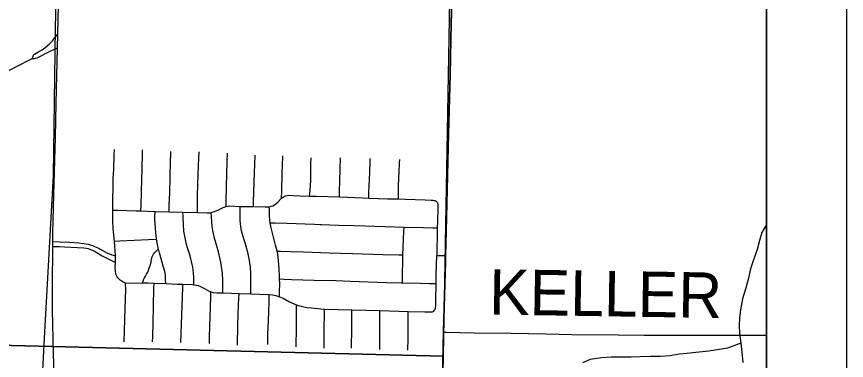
# Model space of a CAD drawing. Extents: x 0 to 34, y 0 to 22.
# Drawn here: x 7.962 to 9, y 16.878 to 17.308 of the extents above; entities that cross this region are included whole.
import ezdxf

# ---------------------------------------------------------------- set-up
doc = ezdxf.new("R2010")
doc.units = 0
for name, color, linetype in [('GM_X_Corporation', 7, 'Continuous'), ('GM_X_County_Road', 7, 'Continuous'), ('GM_X_Minor_River', 7, 'Continuous'), ('GM_X_Township_Road', 7, 'Continuous'), ('GM_X_Township_Road_Text', 7, 'Continuous'), ('SH_Data', 7, 'Continuous')]:
    doc.layers.add(name, color=color, linetype=linetype)

msp = doc.modelspace()

# ---------------------------------------------------------------- linework, layer by layer
at = {"layer": 'GM_X_Corporation'}
for points in [[(2.1, 14.1), (8.9, 14.1), (8.9, 20.9), (5.8906, 20.9)], [(8.9, 14.3789), (8.9, 20.9)], [(8.5071, 17.3567), (8.5056, 17.3001), (8.5042, 17.2361), (8.5017, 17.1453), (8.5005, 17.0919), (8.4991, 17.039), (8.4984, 17.0094), (8.4982, 17.0005), (8.4971, 16.9595), (8.496, 16.9136), (8.4946, 16.8569)], [(8.4946, 16.8569), (8.496, 16.9136), (8.4971, 16.9595), (8.4982, 17.0005), (8.4984, 17.0094), (8.4991, 17.039), (8.5005, 17.0919), (8.5017, 17.1453), (8.5042, 17.2361), (8.5056, 17.3001), (8.5071, 17.3567)]]:
    msp.add_lwpolyline(points, dxfattribs=at)
for points in [[(7.515, 17.8763), (8.5579, 17.8652), (8.5553, 17.7758), (8.5049, 17.4227), (8.4956, 16.8828), (7.4991, 16.9078)], [(8.9, 16.4075), (8.9, 17.4164), (8.5049, 17.4227), (8.4956, 16.8828), (8.4859, 16.4125)], [(7.4991, 16.9078), (8.4956, 16.8828), (8.4859, 16.4125), (8.4788, 15.8782), (7.4758, 15.8976)]]:
    msp.add_lwpolyline(points, close=True, dxfattribs=at)
at = {"layer": 'GM_X_County_Road'}
for points in [[(8.4986, 17.0089), (8.4994, 17.0385), (8.5008, 17.0913), (8.502, 17.1448), (8.5044, 17.2355), (8.5058, 17.2995), (8.5074, 17.3561), (8.5081, 17.3847), (8.5084, 17.3957), (8.5091, 17.4133), (8.51, 17.4274), (8.5107, 17.4362), (8.5114, 17.4424), (8.5122, 17.4492), (8.515, 17.469), (8.5188, 17.4968)], [(8.0128, 17.2691), (8.0132, 17.2859), (8.0142, 17.3225), (8.0154, 17.36), (8.0161, 17.3963), (8.0168, 17.4134)], [(8.007, 17.0204), (8.0071, 17.0264), (8.0072, 17.0373), (8.0083, 17.0851), (8.0105, 17.1572), (8.0113, 17.1998), (8.0128, 17.2691)], [(8.0071, 16.9257), (8.0068, 16.9379), (8.0065, 16.9711), (8.007, 17.0204)], [(8.4962, 16.913), (8.4973, 16.9589), (8.4984, 16.9999), (8.4986, 17.0089)], [(8.0086, 16.8642), (8.0084, 16.8726), (8.0076, 16.9023), (8.0071, 16.9257)], [(8.4945, 16.5973), (8.4945, 16.6238), (8.4942, 16.6866), (8.4941, 16.7015), (8.4942, 16.727), (8.4942, 16.7625), (8.4946, 16.8159), (8.4948, 16.8563), (8.4962, 16.913)]]:
    msp.add_lwpolyline(points, dxfattribs=at)
at = {"layer": 'GM_X_Minor_River'}
for points in [[(7.2928, 17.8115), (7.3401, 17.8018), (7.3986, 17.7904), (7.4434, 17.7823), (7.5003, 17.7732), (7.5467, 17.7696), (7.6442, 17.7695), (7.7568, 17.7696), (7.8864, 17.7695), (7.9974, 17.77), (8.0144, 17.766), (8.0173, 17.7591), (8.0181, 17.7348), (8.0147, 17.6168), (8.0142, 17.4615), (8.0102, 17.2942), (8.0074, 17.1093), (7.9961, 16.9056), (7.99, 16.7846)], [(8.9, 17.0478), (8.8943, 17.0378), (8.8911, 17.028), (8.8884, 17.0166), (8.8833, 17.0023), (8.8801, 16.9924), (8.8769, 16.9788), (8.8733, 16.9656), (8.8698, 16.9546), (8.8674, 16.941), (8.8661, 16.9307), (8.866, 16.9212), (8.8662, 16.911), (8.8679, 16.8992), (8.8693, 16.8882), (8.8703, 16.8752)], [(8.8679, 16.8992), (8.8512, 16.893), (8.8414, 16.8912), (8.8278, 16.8891), (8.8115, 16.8874), (8.8005, 16.8864), (8.7907, 16.8854), (8.7797, 16.8836), (8.7676, 16.8826), (8.7555, 16.8824), (8.7419, 16.8822), (8.7306, 16.8819), (8.7189, 16.8817), (8.7057, 16.8819), (8.6936, 16.8809), (8.6792, 16.8788), (8.6697, 16.8747)]]:
    msp.add_lwpolyline(points, dxfattribs=at)
at = {"layer": 'GM_X_Township_Road'}
for p, q in [((8.1352, 17.0642), (8.1525, 17.0637)), ((8.1525, 17.0637), (8.1698, 17.0633)), ((8.1698, 17.0633), (8.1881, 17.0627)), ((8.0854, 17.0084), (8.0842, 17.0271)), ((8.0854, 17.0004), (8.0854, 17.0084)), ((8.0982, 16.9745), (8.1194, 16.9746)), ((8.1337, 16.9745), (8.1485, 16.974)), ((8.2402, 16.9616), (8.2549, 16.9609)), ((8.3469, 16.942), (8.3813, 16.9411)), ((8.3813, 16.9411), (8.4164, 16.9403)), ((8.4164, 16.9403), (8.4518, 16.9391))]:
    msp.add_line(p, q, dxfattribs=at)
for points in [[(7.9813, 17.2557), (7.9819, 17.2575), (7.9824, 17.2586), (7.983, 17.2597), (7.9843, 17.2612), (7.9885, 17.2635), (7.9937, 17.2665), (7.9972, 17.2689), (8.0024, 17.2734), (8.0069, 17.2782), (8.0089, 17.2806), (8.0132, 17.2859)], [(7.9813, 17.2557), (7.9831, 17.2555), (7.9845, 17.2556), (7.9859, 17.2559), (7.9874, 17.2563), (8.0029, 17.2642), (8.0128, 17.2691)], [(7.7503, 16.8884), (7.7529, 16.8912), (7.7548, 16.894), (7.7567, 16.8973), (7.7644, 16.9127), (7.7819, 16.9464), (7.8021, 16.9856), (7.8201, 17.0204), (7.8294, 17.0387), (7.8501, 17.079), (7.8882, 17.1524), (7.9086, 17.1922), (7.9139, 17.2019), (7.918, 17.2087), (7.9218, 17.2142), (7.926, 17.2193), (7.9305, 17.2242), (7.9353, 17.2287), (7.9404, 17.2329), (7.9464, 17.2371), (7.9537, 17.2415), (7.9617, 17.2457), (7.9813, 17.2557)], [(8.082, 17.0657), (8.082, 17.0682), (8.0828, 17.1048), (8.0833, 17.1172), (8.0839, 17.1352), (8.0841, 17.1417)], [(8.1173, 17.0648), (8.1176, 17.0719), (8.1182, 17.0893), (8.1189, 17.118), (8.1194, 17.1361), (8.1194, 17.1411)], [(8.1525, 17.0637), (8.1528, 17.072), (8.1533, 17.0876), (8.1544, 17.1274), (8.1547, 17.1356), (8.1549, 17.1393)], [(8.1881, 17.0627), (8.1881, 17.0683), (8.188, 17.0838), (8.1885, 17.098), (8.1894, 17.1215), (8.1901, 17.1388)], [(8.2239, 17.0705), (8.2241, 17.0771), (8.2244, 17.0951), (8.2254, 17.1273), (8.2255, 17.1373)], [(8.2581, 17.0702), (8.2583, 17.0764), (8.2595, 17.1124), (8.2602, 17.1341), (8.2602, 17.1347)], [(8.2934, 17.0808), (8.2936, 17.0894), (8.2942, 17.1123), (8.295, 17.1327), (8.295, 17.1339)], [(8.3284, 17.0834), (8.3289, 17.0903), (8.3297, 17.1033), (8.3301, 17.1244), (8.3303, 17.1313)], [(8.3656, 17.0823), (8.3658, 17.0887), (8.3672, 17.1311)], [(8.4023, 17.0809), (8.4026, 17.0879), (8.4037, 17.1128), (8.4041, 17.1266), (8.4041, 17.1304)], [(8.4395, 17.0798), (8.4396, 17.0855), (8.4398, 17.0968), (8.4405, 17.1142), (8.4409, 17.1242), (8.4412, 17.1291)], [(8.2776, 17.0701), (8.2801, 17.0706), (8.2823, 17.0713), (8.2844, 17.0723), (8.2863, 17.0737), (8.2889, 17.0762), (8.2923, 17.0799), (8.2934, 17.0808)], [(8.2934, 17.0808), (8.2943, 17.0816), (8.2965, 17.083), (8.2984, 17.0838), (8.3003, 17.0842), (8.3029, 17.0845), (8.308, 17.0842), (8.316, 17.0839), (8.3284, 17.0834)], [(8.3284, 17.0834), (8.3371, 17.0831), (8.3656, 17.0823)], [(8.3656, 17.0823), (8.3955, 17.0812), (8.4023, 17.0809)], [(8.4023, 17.0809), (8.4259, 17.0801), (8.4395, 17.0798)], [(8.4395, 17.0798), (8.4483, 17.0796), (8.4731, 17.0787), (8.4806, 17.0783), (8.4827, 17.0781), (8.4838, 17.078), (8.4849, 17.0778), (8.4857, 17.0776), (8.4867, 17.0771), (8.4874, 17.0764), (8.488, 17.0755), (8.4884, 17.0749), (8.4885, 17.0741), (8.4886, 17.0734), (8.4886, 17.0727), (8.4886, 17.0718), (8.4887, 17.0682), (8.4883, 17.0514), (8.4881, 17.0437)], [(8.2053, 17.0629), (8.2063, 17.0631), (8.2092, 17.064), (8.2143, 17.0662), (8.2204, 17.0693), (8.2239, 17.0705)], [(8.2239, 17.0705), (8.226, 17.0708), (8.2284, 17.0711), (8.2413, 17.0705)], [(8.2413, 17.0705), (8.2555, 17.0702), (8.2581, 17.0702)], [(8.2549, 16.9609), (8.2549, 16.9664), (8.2549, 16.9863), (8.2543, 16.9946), (8.2531, 17.0027), (8.2514, 17.0113), (8.2486, 17.0221), (8.2448, 17.034), (8.2433, 17.0399), (8.2424, 17.0454), (8.2415, 17.0527), (8.2414, 17.057), (8.2413, 17.0705)], [(8.2581, 17.0702), (8.2729, 17.0698), (8.2765, 17.07), (8.2776, 17.0701)], [(8.2792, 17.05), (8.2785, 17.0534), (8.2781, 17.0587), (8.2782, 17.0637), (8.278, 17.0662), (8.2776, 17.0701)], [(8.082, 17.0657), (8.0879, 17.0656), (8.1115, 17.065), (8.1173, 17.0648)], [(8.0842, 17.0271), (8.0826, 17.0427), (8.0821, 17.052), (8.082, 17.0657)], [(8.1173, 17.0648), (8.1333, 17.0643), (8.1352, 17.0642)], [(8.137, 17.0294), (8.1358, 17.0381), (8.135, 17.0481), (8.1348, 17.0543), (8.1349, 17.0581), (8.1352, 17.0642)], [(8.1836, 16.9724), (8.1835, 16.9753), (8.1835, 16.9814), (8.1831, 16.9867), (8.1828, 16.9909), (8.1822, 16.9946), (8.1815, 16.9978), (8.1808, 17.0014), (8.1788, 17.0084), (8.1772, 17.0138), (8.1755, 17.0188), (8.1743, 17.0229), (8.1725, 17.0311), (8.1712, 17.0396), (8.1705, 17.0476), (8.1701, 17.0575), (8.1698, 17.0633)], [(8.1881, 17.0627), (8.2004, 17.0624), (8.2034, 17.0626), (8.2053, 17.0629)], [(8.2197, 16.9622), (8.2197, 16.9681), (8.2197, 16.9774), (8.2192, 16.9867), (8.2183, 16.9953), (8.2174, 17.0008), (8.2142, 17.0134), (8.2093, 17.0308), (8.2076, 17.0382), (8.2065, 17.045), (8.2059, 17.0519), (8.2056, 17.0569), (8.2053, 17.0629)], [(8.2878, 17.0145), (8.2874, 17.0166), (8.2859, 17.0219), (8.2808, 17.0418), (8.28, 17.0458), (8.2792, 17.05)], [(8.2792, 17.05), (8.2851, 17.0498), (8.3, 17.0494), (8.3347, 17.0482), (8.3415, 17.0478), (8.3434, 17.0477), (8.3645, 17.0471), (8.3844, 17.0467), (8.4228, 17.0454), (8.4466, 17.0446)], [(8.4452, 17.0097), (8.4464, 17.0392), (8.4466, 17.0446)], [(8.4466, 17.0446), (8.4708, 17.0439), (8.4824, 17.0438), (8.4881, 17.0437)], [(8.4881, 17.0437), (8.4879, 17.0341), (8.4875, 17.0167), (8.4875, 17.0089)], [(8.0842, 17.0271), (8.091, 17.0274), (8.127, 17.029), (8.137, 17.0294)], [(8.1394, 17.0172), (8.1385, 17.0208), (8.137, 17.0294)], [(8.007, 17.0204), (8.0153, 17.0201), (8.0219, 17.02), (8.038, 17.0191), (8.0458, 17.0185), (8.0493, 17.0181), (8.0514, 17.0176), (8.0534, 17.017), (8.0563, 17.0159), (8.0589, 17.0147), (8.0612, 17.0132), (8.0689, 17.0087), (8.073, 17.0066), (8.0854, 17.0004)], [(8.0071, 17.0264), (8.0155, 17.0261), (8.0285, 17.0256), (8.0396, 17.0247), (8.0457, 17.024), (8.0513, 17.023), (8.054, 17.0224), (8.0567, 17.0215), (8.0594, 17.0203), (8.0633, 17.0185), (8.0709, 17.0143), (8.0753, 17.012), (8.0778, 17.011), (8.0809, 17.0099), (8.0854, 17.0084)], [(8.1194, 16.9746), (8.1207, 16.9786), (8.1217, 16.9811), (8.123, 16.9833), (8.1245, 16.9856), (8.1258, 16.988), (8.1269, 16.9906), (8.1281, 16.9944), (8.1292, 16.9978), (8.1301, 17.0008), (8.1307, 17.0045), (8.1315, 17.0073), (8.1322, 17.0091), (8.1332, 17.0108), (8.1343, 17.0123), (8.136, 17.014), (8.1394, 17.0172)], [(8.1485, 16.974), (8.1482, 16.9794), (8.1479, 16.9843), (8.1471, 16.9891), (8.1457, 16.9944), (8.1406, 17.0123), (8.1394, 17.0172)], [(8.2878, 17.0145), (8.2919, 17.0144), (8.305, 17.014), (8.3206, 17.0134), (8.3529, 17.0124), (8.3822, 17.0115), (8.4202, 17.0104), (8.4401, 17.0099), (8.4452, 17.0097)], [(8.2908, 16.9796), (8.2908, 16.9828), (8.2901, 16.9927), (8.2891, 17.007), (8.2885, 17.0107), (8.2878, 17.0145)], [(8.4445, 16.9749), (8.4447, 16.9843), (8.445, 17.0036), (8.4452, 17.0097)], [(8.4868, 16.9739), (8.4869, 16.9852), (8.4875, 17.0089)], [(8.4875, 17.0089), (8.4957, 17.0089), (8.4986, 17.0089)], [(8.0982, 16.9745), (8.0972, 16.9748), (8.0962, 16.9752), (8.0949, 16.9758), (8.0938, 16.9765), (8.0921, 16.9776), (8.0912, 16.9783), (8.09, 16.9793), (8.0891, 16.9803), (8.0885, 16.9812), (8.0878, 16.9822), (8.0871, 16.9833), (8.0867, 16.984), (8.0864, 16.9849), (8.086, 16.9857), (8.0858, 16.987), (8.0856, 16.9884), (8.0854, 16.9899), (8.0853, 16.9921), (8.0853, 16.9947), (8.0854, 17.0004)], [(8.2905, 16.9574), (8.2907, 16.9636), (8.291, 16.9735), (8.2908, 16.9796)], [(8.2908, 16.9796), (8.2965, 16.9794), (8.3058, 16.9789), (8.3339, 16.978), (8.3613, 16.9776), (8.3793, 16.9769), (8.4247, 16.9753), (8.4434, 16.975), (8.4445, 16.9749)], [(8.0962, 16.9008), (8.0978, 16.9429), (8.0983, 16.966), (8.0982, 16.9745)], [(8.1194, 16.9746), (8.1265, 16.9747), (8.1337, 16.9745)], [(8.1319, 16.901), (8.1321, 16.9074), (8.1325, 16.9241), (8.1335, 16.9675), (8.1337, 16.9745)], [(8.1485, 16.974), (8.1631, 16.9732), (8.1699, 16.973)], [(8.1674, 16.8999), (8.1697, 16.969), (8.1699, 16.973)], [(8.1699, 16.973), (8.1817, 16.9726), (8.1836, 16.9724)], [(8.1836, 16.9724), (8.1865, 16.972), (8.1888, 16.9714), (8.191, 16.9706), (8.1959, 16.968), (8.202, 16.9647), (8.2048, 16.9636)], [(8.4445, 16.9749), (8.4677, 16.9742), (8.4783, 16.974), (8.4868, 16.9739)], [(8.4518, 16.9391), (8.4726, 16.9385), (8.4768, 16.9386), (8.4799, 16.9386), (8.4811, 16.9386), (8.482, 16.9387), (8.483, 16.939), (8.4838, 16.9394), (8.4847, 16.9405), (8.4852, 16.9413), (8.4854, 16.942), (8.4857, 16.9429), (8.4859, 16.9438), (8.486, 16.9446), (8.4862, 16.9454), (8.4862, 16.9463), (8.4863, 16.9475), (8.4865, 16.9536), (8.4868, 16.9739)], [(8.2032, 16.8988), (8.2032, 16.9074), (8.2046, 16.9577), (8.2048, 16.9636)], [(8.2048, 16.9636), (8.2081, 16.9628), (8.2125, 16.9623), (8.2197, 16.9622)], [(8.2197, 16.9622), (8.2305, 16.9618), (8.2402, 16.9616)], [(8.2383, 16.8968), (8.2387, 16.9214), (8.2394, 16.9482), (8.2398, 16.9549), (8.2402, 16.9616)], [(8.2549, 16.9609), (8.277, 16.96), (8.2778, 16.96)], [(8.2759, 16.8976), (8.2762, 16.9099), (8.2766, 16.9192), (8.2772, 16.9372), (8.2777, 16.9533), (8.2778, 16.96)], [(8.2778, 16.96), (8.2819, 16.9596), (8.2861, 16.9588), (8.2905, 16.9574)], [(8.2905, 16.9574), (8.2952, 16.9554), (8.3034, 16.951), (8.3097, 16.9481), (8.3121, 16.9472)], [(8.3115, 16.8945), (8.3118, 16.919), (8.3121, 16.9413), (8.3121, 16.9472)], [(8.3121, 16.9472), (8.3144, 16.9463), (8.3193, 16.945), (8.3248, 16.944), (8.3311, 16.9433), (8.3426, 16.9422), (8.3469, 16.942)], [(8.3465, 16.8928), (8.3467, 16.914), (8.3469, 16.9389), (8.3469, 16.942)], [(8.3809, 16.893), (8.3809, 16.8968), (8.381, 16.9142), (8.3813, 16.9361), (8.3813, 16.9411)], [(8.4162, 16.8913), (8.4163, 16.8947), (8.4164, 16.9403)], [(8.4514, 16.8907), (8.4517, 16.9045), (8.4518, 16.9331), (8.4518, 16.9391)], [(8.4962, 16.913), (8.4992, 16.913), (8.5341, 16.9124), (8.5802, 16.9116), (8.6242, 16.9108), (8.6566, 16.9103), (8.7144, 16.9096), (8.7471, 16.9093), (8.7747, 16.9091), (8.8201, 16.9092), (8.8653, 16.9093), (8.9, 16.9092)]]:
    msp.add_lwpolyline(points, dxfattribs=at)
at = {"layer": 'SH_Data'}
for p, q in [((9, 21), (9, 14)), ((9, 21), (9, 14)), ((8.9, 20.9), (8.9, 14.1)), ((8.9, 20.9), (8.9, 14.1))]:
    msp.add_line(p, q, dxfattribs=at)

# ---------------------------------------------------------------- texts
at = {"layer": 'GM_X_Township_Road_Text'}
msp.add_text('KELLER', height=0.05682, rotation=359.1142, dxfattribs=at).set_placement((8.5527, 16.9352))

doc.saveas('drawing.dxf')
